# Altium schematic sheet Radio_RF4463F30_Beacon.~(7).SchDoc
size A4
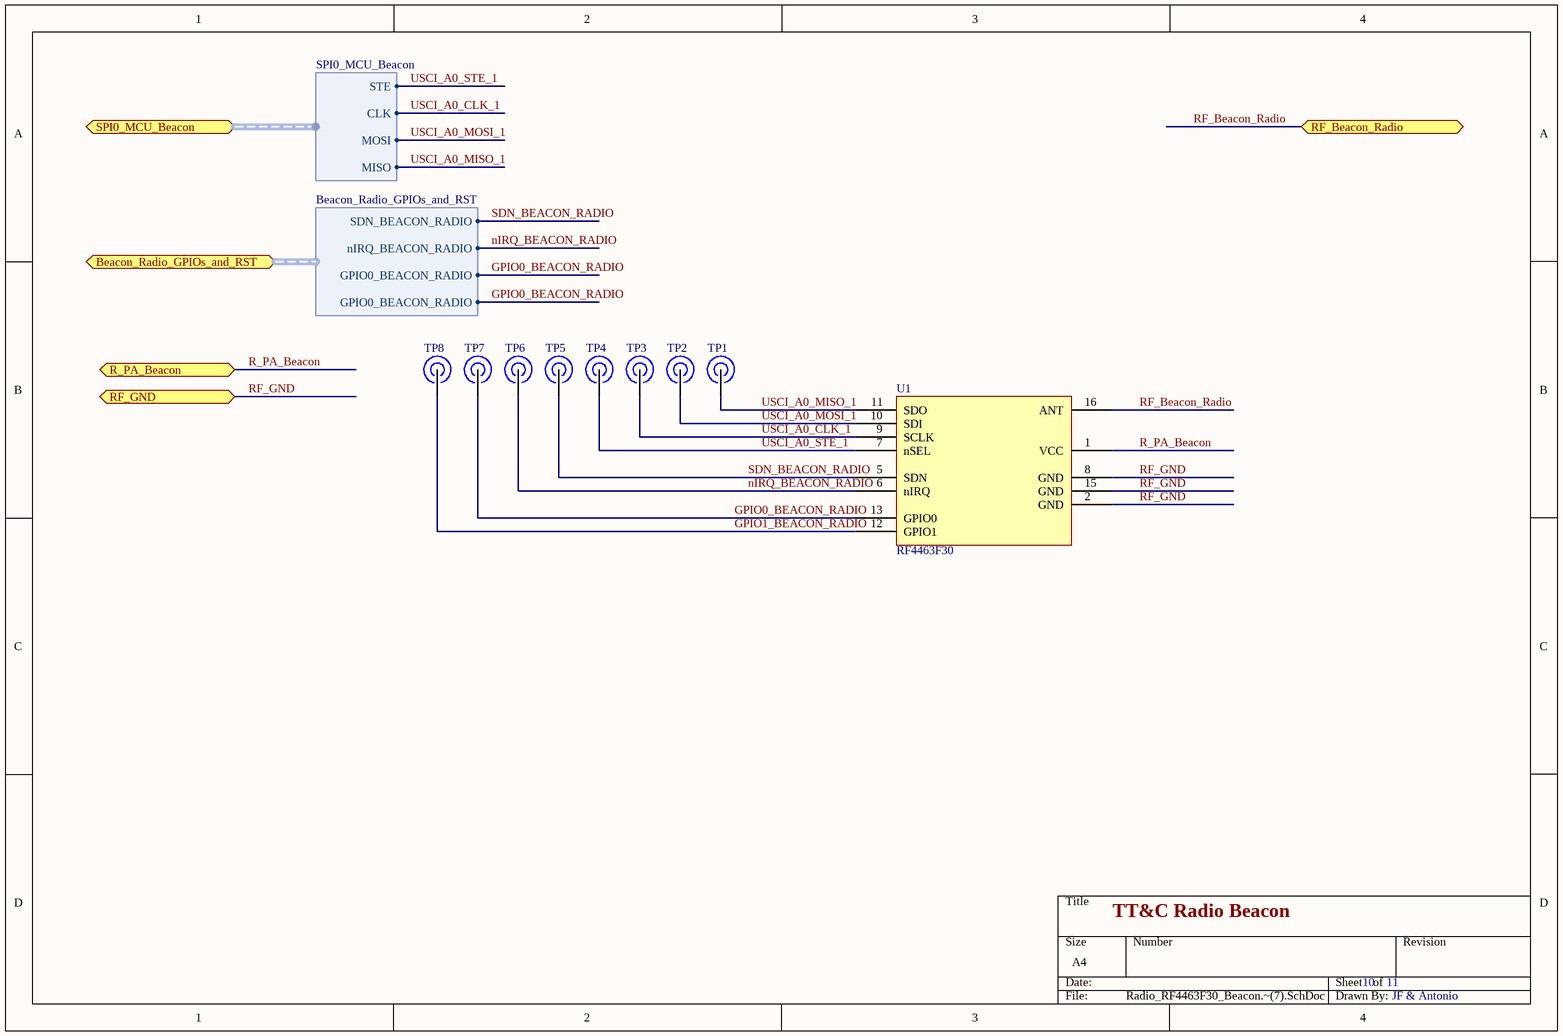
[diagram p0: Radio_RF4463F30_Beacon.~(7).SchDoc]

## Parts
TP1  TestPoint  [TESTPOINT_2x2mm]  (value not drawn)
TP2  TestPoint  [TESTPOINT_2x2mm]  (value not drawn)
TP3  TestPoint  [TESTPOINT_2x2mm]  (value not drawn)
TP4  TestPoint  [TESTPOINT_2x2mm]  (value not drawn)
TP5  TestPoint  [TESTPOINT_2x2mm]  (value not drawn)
TP6  TestPoint  [TESTPOINT_2x2mm]  (value not drawn)
TP7  TestPoint  [TESTPOINT_2x2mm]  (value not drawn)
TP8  TestPoint  [TESTPOINT_2x2mm]  (value not drawn)
U1  RF4463F30

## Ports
Beacon_Radio_GPIOs_and_RST (harness Beacon_Radio_GPIOs_and_RST), R_PA_Beacon, RF_Beacon_Radio, RF_GND, SPI0_MCU_Beacon (harness SPI0_MCU_Beacon)

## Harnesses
SPI0_MCU_Beacon: STE, CLK, MOSI, MISO
Beacon_Radio_GPIOs_and_RST: SDN_BEACON_RADIO, nIRQ_BEACON_RADIO, GPIO0_BEACON_RADIO, GPIO0_BEACON_RADIO

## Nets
GPIO0_BEACON_RADIO: TP7.1 U1.13(GPIO0) ; port Beacon_Radio_GPIOs_and_RST.GPIO0_BEACON_RADIO
GPIO1_BEACON_RADIO: TP8.1 U1.12(GPIO1)
nIRQ_BEACON_RADIO: TP6.1 U1.6(nIRQ) ; port Beacon_Radio_GPIOs_and_RST.nIRQ_BEACON_RADIO
R_PA_Beacon: U1.1(VCC) ; port R_PA_Beacon
RF_Beacon_Radio: U1.16(ANT) ; port RF_Beacon_Radio
RF_GND: U1.2(GND) U1.8(GND) U1.15(GND) ; port RF_GND
SDN_BEACON_RADIO: TP5.1 U1.5(SDN) ; port Beacon_Radio_GPIOs_and_RST.SDN_BEACON_RADIO
USCI_A0_CLK_1: TP3.1 U1.9(SCLK) ; port SPI0_MCU_Beacon.CLK
USCI_A0_MISO_1: TP1.1 U1.11(SDO) ; port SPI0_MCU_Beacon.MISO
USCI_A0_MOSI_1: TP2.1 U1.10(SDI) ; port SPI0_MCU_Beacon.MOSI
USCI_A0_STE_1: TP4.1 U1.7(nSEL) ; port SPI0_MCU_Beacon.STE

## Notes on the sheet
- TT&C Radio Beacon
- 10
- 11
- JF & Antonio

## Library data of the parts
TP1-TP8 = TestPoint: Punto de prueba de 3x3mm; pin to pad: 1>TP; PCB DECAL: TestPoint XxXmm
